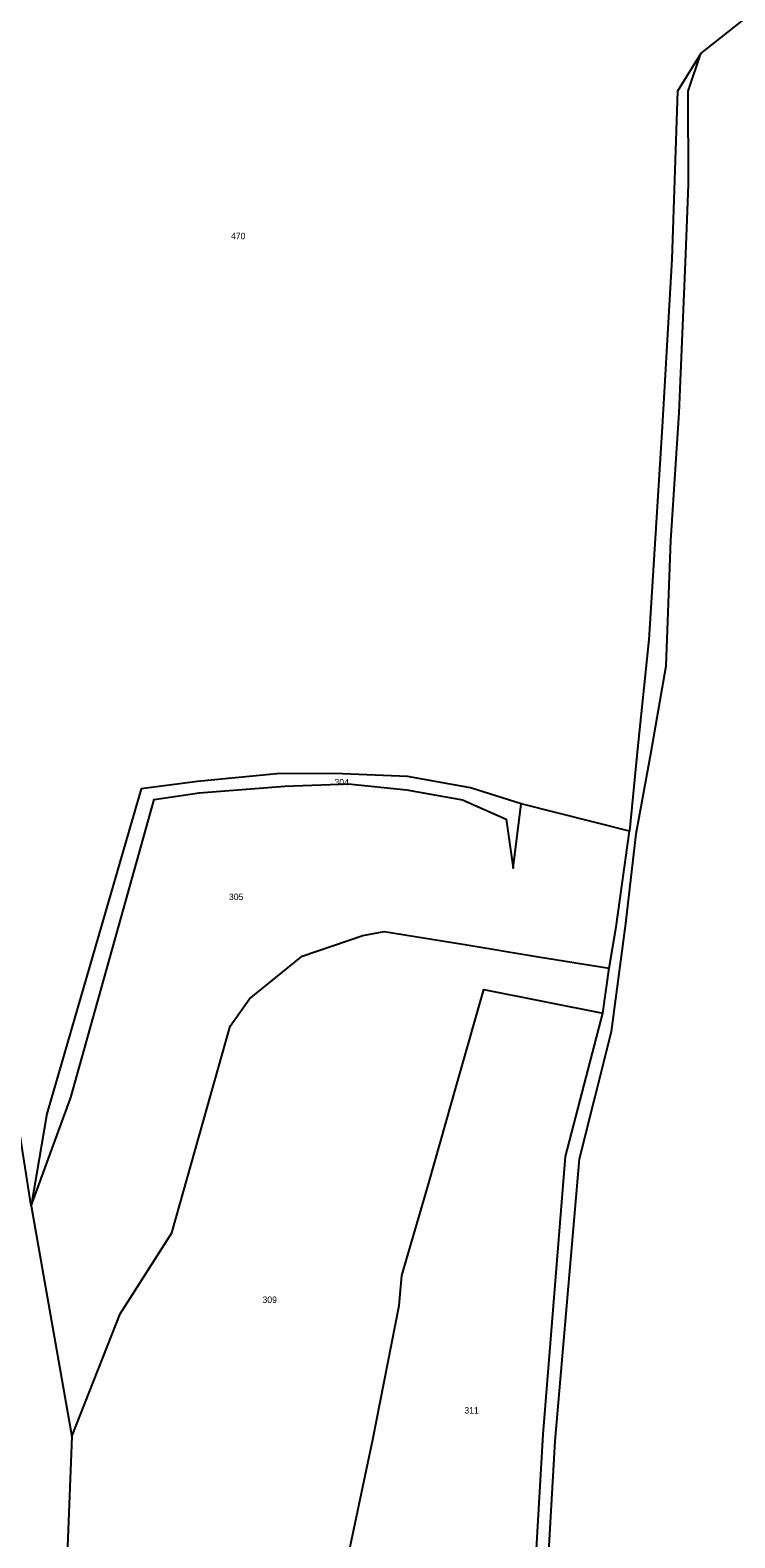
# Model space of a CAD drawing. Extents: x -880531 to -877616, y -1023932 to -1021350.
# Drawn here: x -878804.4 to -878618.7, y -1021964.1 to -1021566.9 of the extents above; entities that cross this region are included whole.
import ezdxf

# ---------------------------------------------------------------- set-up
doc = ezdxf.new("R2010")
doc.units = 0
doc.layers.add('Hranice parcel', color=7, linetype='Continuous')
doc.layers.add('Parcelní čísla', color=7, linetype='Continuous')

msp = doc.modelspace()

# ---------------------------------------------------------------- linework, layer by layer
at = {"layer": 'Hranice parcel'}
for p, q in [((-878627.58, -1021573.01), (-878545.85, -1021507.93)), ((-878646.44, -1021777.85), (-878674.95, -1021770.72)), ((-878653.45, -1021825.8), (-878651.8, -1021814.01)), ((-878804.12, -1021876.63), (-878793.35, -1021937.32)), ((-878793.35, -1021937.32), (-878795.54, -1021993.32))]:
    msp.add_line(p, q, dxfattribs=at)
for points in [[(-878693.21, -1022298.36), (-878692.4, -1022258.3), (-878689.78, -1022213.59), (-878684.22, -1022158.54), (-878682.26, -1022103.14), (-878673.47, -1022036.72), (-878669.09, -1021992.24), (-878665.96, -1021938.56), (-878659.56, -1021864.21), (-878651.12, -1021830.64), (-878647.4, -1021802.19), (-878644.62, -1021778.59), (-878640.81, -1021757.55), (-878636.77, -1021734.3), (-878635.51, -1021701.34), (-878633.33, -1021667.69), (-878631.59, -1021625.86), (-878630.9, -1021607.55), (-878630.94, -1021582.96), (-878627.58, -1021573.01)], [(-878627.58, -1021573.01), (-878633.77, -1021582.98), (-878635.3, -1021627.16), (-878637.78, -1021671.37), (-878641.3, -1021727.37), (-878644.38, -1021757.08), (-878646.44, -1021777.85)], [(-878804.12, -1021876.63), (-878809.97, -1021839.01), (-878819.28, -1021809.84), (-878832.16, -1021783), (-878846.89, -1021759.47), (-878908.97, -1021689.26)], [(-878674.95, -1021770.72), (-878688.33, -1021766.49), (-878704.95, -1021763.52), (-878724.13, -1021762.71), (-878739.39, -1021762.8), (-878760.25, -1021764.84), (-878775.12, -1021766.73), (-878799.98, -1021852.31), (-878804.12, -1021876.63)], [(-878804.12, -1021876.63), (-878793.67, -1021848.08), (-878771.63, -1021769.53), (-878759.82, -1021767.77), (-878737.2, -1021766.01), (-878720.51, -1021765.44), (-878705.18, -1021767.02), (-878690.39, -1021769.59), (-878678.89, -1021774.76), (-878677.05, -1021787.65), (-878674.95, -1021770.72)], [(-878651.8, -1021814.01), (-878649.92, -1021803.12), (-878646.44, -1021777.85)], [(-878793.35, -1021937.32), (-878780.66, -1021905.08), (-878767.06, -1021883.73), (-878751.67, -1021829.27), (-878746.58, -1021822.1), (-878732.64, -1021810.86), (-878716.67, -1021805.33), (-878711.07, -1021804.31), (-878689.82, -1021807.7), (-878670.42, -1021810.96), (-878651.8, -1021814.01)], [(-878738.23, -1022017.29), (-878723.26, -1021981.78), (-878714.09, -1021938.14), (-878707.13, -1021902.81), (-878706.39, -1021894.96), (-878699.38, -1021870.84), (-878691.7, -1021843.88), (-878684.82, -1021819.64), (-878653.45, -1021825.8)], [(-878676.69, -1022035.16), (-878672.32, -1021991.2), (-878669.14, -1021936.84), (-878663.28, -1021863.62), (-878653.45, -1021825.8)]]:
    msp.add_lwpolyline(points, dxfattribs=at)

# ---------------------------------------------------------------- texts
at = {"layer": 'Parcelní čísla'}
for s, p in [('470', (-878751.43, -1021621.94)), ('304', (-878724.14, -1021765.83)), ('305', (-878751.95, -1021796.03)), ('309', (-878743.12, -1021902.18)), ('311', (-878689.92, -1021931.31))]:
    msp.add_text(s, height=1.7, dxfattribs=at).set_placement(p)

doc.saveas('drawing.dxf')
